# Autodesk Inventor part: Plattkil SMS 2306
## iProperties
Author: Morgan
Shininess: 41.0
Length Units: 11269
Angle Units: 11283
Time Units: 11279
Mass Units: 11290
Length Display Precision: 2
Angle Display Precision: 2
Compacted: True
PropertySet Name: _Private Model Information
Created: 2001-10
Part Number: Plattkil SMS 2306
Material: SS 1312
Document SubType Name: Modeling
Designer: Morgan
Control State: 0
Master: False
Checked Out: False
PropertySet Name: Design Tracking Control
Density: 0.0
Volumn: 0.0
Area: 0.0
PropertySet Name: Model Information
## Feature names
1. Extrusion1
2. Chamfer1
